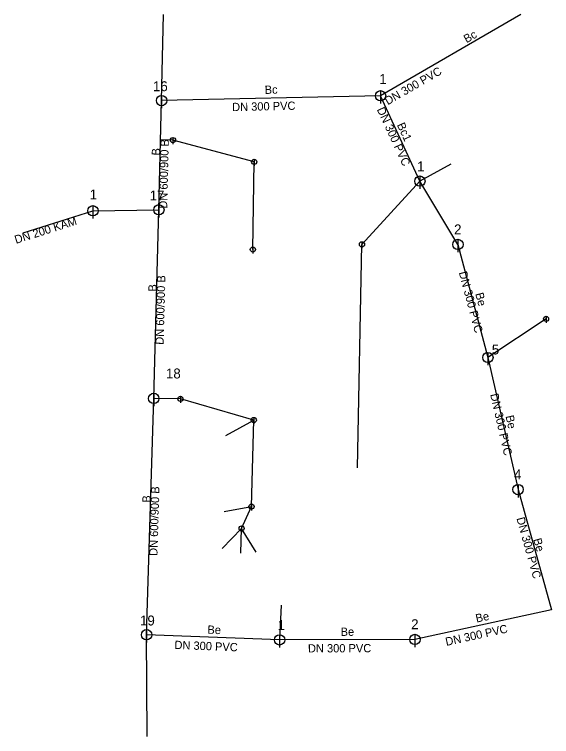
# Model space of a CAD drawing. Extents: x -464832 to -464727, y -1094758 to -1094618.
import ezdxf

# ---------------------------------------------------------------- set-up
doc = ezdxf.new("R2010")
doc.units = 0
for name, color, linetype in [('_pripojka_kanal_jednotna_prevzato_z_dokumentace_', 7, 'Continuous'), ('_pripojka_kanal_jednotna_priblizne_', 7, 'Continuous'), ('_stoka_jednotna_smvak_prevzato_z_dokumentace_', 7, 'Continuous'), ('Default', 7, 'Continuous'), ('MoLevel 119', 7, 'Continuous'), ('MoLevel 120', 7, 'Continuous'), ('MoLevel 124', 7, 'Continuous'), ('MoLevel 57', 7, 'Continuous'), ('MoLevel 68', 7, 'Continuous'), ('MoLevel 69', 7, 'Continuous')]:
    doc.layers.add(name, color=color, linetype=linetype)

# ---------------------------------------------------------------- blocks, each defined once
blk = doc.blocks.new('_sachta_kanal_prip_')
at = {"layer": 'Default'}
blk.add_line((0, 0.00005), (0, -0.000075), dxfattribs=at)
blk.add_circle((0, 0), 0.00005, dxfattribs=at)
blk = doc.blocks.new('_sachta_kanal_prevzato_z_dokumentace_')
at = {"layer": 'Default'}
blk.add_line((0, 0.00005), (0, -0.000075), dxfattribs=at)
blk.add_circle((0, 0), 0.00005, dxfattribs=at)

msp = doc.modelspace()

# ---------------------------------------------------------------- linework, layer by layer
at = {"layer": '_pripojka_kanal_jednotna_prevzato_z_dokumentace_'}
for p, q in [((-464800.91, -1094641.98), (-464803.31, -1094641.92)), ((-464785.15, -1094646.2), (-464800.91, -1094641.98)), ((-464785.41, -1094663.18), (-464785.15, -1094646.2)), ((-464747.03, -1094646.65), (-464753.02, -1094649.93)), ((-464764.25, -1094662.18), (-464753.02, -1094649.93)), ((-464765.12, -1094705.53), (-464764.25, -1094662.18)), ((-464728.54, -1094676.63), (-464739.82, -1094684.12)), ((-464799.47, -1094692.14), (-464804.64, -1094692.05)), ((-464785.23, -1094696.24), (-464799.47, -1094692.14)), ((-464790.65, -1094699.26), (-464785.23, -1094696.24)), ((-464785.67, -1094713.01), (-464785.23, -1094696.24)), ((-464790.99, -1094713.99), (-464785.67, -1094713.01)), ((-464787.6, -1094717.25), (-464785.67, -1094713.01)), ((-464791.36, -1094721.15), (-464787.6, -1094717.25)), ((-464787.72, -1094722.03), (-464787.6, -1094717.25)), ((-464784.76, -1094721.84), (-464787.6, -1094717.25)), ((-464779.93, -1094732.15), (-464780.23, -1094738.87))]:
    msp.add_line(p, q, dxfattribs=at)
at = {"layer": '_pripojka_kanal_jednotna_priblizne_'}
msp.add_line((-464829.94, -1094659.97), (-464816.43, -1094655.68), dxfattribs=at)
at = {"layer": '_stoka_jednotna_smvak_prevzato_z_dokumentace_'}
for p, q in [((-464803.12, -1094634.31), (-464802.72, -1094617.61)), ((-464733.44, -1094617.61), (-464760.64, -1094633.38)), ((-464760.64, -1094633.38), (-464803.12, -1094634.31)), ((-464753.02, -1094649.93), (-464760.64, -1094633.38)), ((-464803.65, -1094655.48), (-464803.12, -1094634.31)), ((-464745.63, -1094662.21), (-464753.02, -1094649.93)), ((-464816.43, -1094655.68), (-464803.65, -1094655.48)), ((-464804.64, -1094692.05), (-464803.65, -1094655.48)), ((-464745.63, -1094662.21), (-464739.82, -1094684.12)), ((-464739.82, -1094684.12), (-464733.97, -1094709.73)), ((-464806.02, -1094737.87), (-464804.64, -1094692.05)), ((-464733.97, -1094709.73), (-464727.47, -1094733.01)), ((-464727.47, -1094733.01), (-464753.97, -1094738.79)), ((-464780.23, -1094738.87), (-464806.02, -1094737.87)), ((-464805.9, -1094757.61), (-464806.02, -1094737.87)), ((-464753.97, -1094738.79), (-464780.23, -1094738.87))]:
    msp.add_line(p, q, dxfattribs=at)

# ---------------------------------------------------------------- block references
at = {"layer": 'MoLevel 119', "xscale": 20000, "yscale": 20000}
for p in [(-464803.12, -1094634.31), (-464760.64, -1094633.38), (-464753.02, -1094649.93), (-464816.43, -1094655.68), (-464803.65, -1094655.48), (-464745.63, -1094662.21), (-464739.82, -1094684.12), (-464804.64, -1094692.05), (-464733.97, -1094709.73), (-464806.02, -1094737.87), (-464780.23, -1094738.87), (-464753.97, -1094738.79)]:
    msp.add_blockref('_sachta_kanal_prevzato_z_dokumentace_', p, dxfattribs=at)
at = {"layer": 'MoLevel 57', "xscale": 10000, "yscale": 10000}
for p in [(-464800.91, -1094641.98), (-464785.15, -1094646.2), (-464785.41, -1094663.18), (-464764.25, -1094662.18), (-464728.54, -1094676.63), (-464799.47, -1094692.14), (-464785.23, -1094696.24), (-464785.67, -1094713.01), (-464787.6, -1094717.25)]:
    msp.add_blockref('_sachta_kanal_prip_', p, dxfattribs=at)

# ---------------------------------------------------------------- texts
at = {"layer": 'MoLevel 120'}
for s, height, p in [('1', 1.93, (-464760.89, -1094631.09)), ('16', 1.926, (-464804.79, -1094632.49)), ('1', 1.93, (-464753.55, -1094648.03)), ('1', 1.93, (-464817.06, -1094653.48)), ('17', 1.926, (-464805.43, -1094653.68)), ('2', 1.93, (-464746.38, -1094660.25)), ('5', 1.93, (-464739.06, -1094683.53)), ('18', 1.926, (-464802.27, -1094688.18)), ('4', 1.93, (-464734.76, -1094707.76)), ('19', 1.926, (-464807.3, -1094736.07)), ('1', 1.93, (-464780.61, -1094736.96)), ('2', 1.93, (-464754.71, -1094736.8))]:
    msp.add_text(s, height=height, dxfattribs=at).set_placement(p)
at = {"layer": 'MoLevel 124'}
msp.add_text('DN 200 KAM', height=1.605, rotation=17.6269, dxfattribs=at).set_placement((-464831.35, -1094662.1))
at = {"layer": 'MoLevel 68'}
for s, height, rotation, p in [('DN 300 PVC', 1.605, 30.1013, (-464759.24, -1094635.23)), ('DN 300 PVC', 1.605, 1.2542, (-464789.42, -1094636.36)), ('DN 300 PVC', 1.605, 294.7224, (-464761.4, -1094636.02)), ('DN 600/900 B', 1.6049, 88.5659, (-464802.04, -1094655.28)), ('DN 600/900 B', 1.6049, 88.4493, (-464802.73, -1094681.67)), ('DN 300 PVC', 1.605, 284.8516, (-464745.47, -1094667.64)), ('DN 300 PVC', 1.605, 282.8671, (-464739.39, -1094691.28)), ('DN 600/900 B', 1.6049, 88.2749, (-464803.93, -1094722.6)), ('DN 300 PVC', 1.605, 285.6003, (-464734.3, -1094715.31)), ('DN 300 PVC', 1.605, 12.3043, (-464747.88, -1094740.04)), ('DN 300 PVC', 1.605, 357.7795, (-464800.65, -1094740.62)), ('DN 300 PVC', 1.605, 0.1746, (-464774.73, -1094741.31))]:
    msp.add_text(s, height=height, rotation=rotation, dxfattribs=at).set_placement(p)
at = {"layer": 'MoLevel 69'}
for s, height, rotation, p in [('Bc', 1.605, 30.1013, (-464743.95, -1094623.21)), ('Bc', 1.605, 1.2542, (-464783.11, -1094633.02)), ('Bc1', 1.605, 294.7224, (-464757.51, -1094639.02)), ('B', 1.6, 88.5659, (-464803.43, -1094644.97)), ('B', 1.6, 88.4493, (-464804.1, -1094671.35)), ('Be', 1.605, 284.8516, (-464742.29, -1094671.76)), ('Be', 1.605, 282.8671, (-464736.41, -1094695.5)), ('B', 1.6, 88.2749, (-464805.27, -1094712.28)), ('Be', 1.605, 285.6003, (-464731.05, -1094719.39)), ('Be', 1.605, 12.3043, (-464742.02, -1094735.52)), ('Be', 1.605, 357.7795, (-464794.25, -1094737.66)), ('Be', 1.605, 0.1746, (-464768.39, -1094738.09))]:
    msp.add_text(s, height=height, rotation=rotation, dxfattribs=at).set_placement(p)

doc.saveas('drawing.dxf')
